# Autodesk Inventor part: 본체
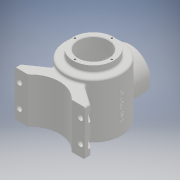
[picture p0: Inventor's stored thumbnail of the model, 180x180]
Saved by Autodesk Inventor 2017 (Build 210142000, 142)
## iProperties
Part Number: 본체
Material: 일반
Document SubType Name: Modeling
Designer: MRC
Density: 1 g/cm^3
Appearance: 기본값
Author: MRC
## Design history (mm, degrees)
sketch "스케치1"
  geometry: L1 (0, 50)-(0, -58); L2 (50, 50)-(50, -46.336); L3 (50, 50)-(0, 50); A1 r 113 centre (0, 55) between (0, -58) and (50, -46.336); 1 further point
  constraints: 6 end point, 2 point on circle, 2 point on line, 2 vertical, 1 centre point, 1 horizontal
  dimensions: "d0" = 108 distance of L1.start L1.end; "d1" = 50 distance of L1.start point (0, 0); "d3" = 100 diameter of L2 L1; "d4" = 113 radius of A1
revolve "회전1" sketch "스케치1" stored, may be unused: angle "d5" = 90 deg
feature "쉘1" dims "d6" = 7
sketch "스케치2"
  geometry: C1 r 36 at (0, 0); 1 further point
  constraints: 1 centre point, 1 coincident
  dimensions: "d7" = 72 diameter of C1
extrude "돌출1" join sketch "스케치2" distance "d8" = 12; taper "d9" = 0 deg
sketch "스케치3"
  geometry: C1 r 27 at (0, 0); 1 further point
  constraints: 1 centre point, 1 coincident
  dimensions: "d10" = 54 diameter of C1
extrude "돌출2" cut sketch "스케치3" distance "d11" = 19; taper "d12" = 0 deg
sketch "스케치4"
  geometry: L1 (-26.694, -42.278)-(-62, -67); L2 (-62, -67)-(-62, -77); L3 (-62, -77)-(-38.5, -77); L4 (38.5, -77)-(62, -77); L5 (62, -77)-(62, -67); L6 (62, -67)-(26.694, -42.278); A1 r 52.096 centre (0, -112.096) between (38.5, -77) and (-38.5, -77); A2 r 50 centre (0, 0) between (26.694, -42.278) and (-26.694, -42.278) reference; 1 further point
  constraints: 12 end point, 4 point on circle, 2 perpendicular, 1 centre point, 1 collinear, 1 horizontal, 1 vertical, 1 vertical alignment
  dimensions: "d13" = 10 distance of L4.end L5.end; "d14" = 77 distance of L4.start L3.end; "d15" = 55 deg angle of L5 L6; "d16" = 10 distance of L1.end L2.end; "d17" = 77 distance from line of L4 point (0, 0); "d18" = 77 distance from line of point (0, 0) L3; "d19" = 124 distance between parallel lines of L5 L2; "d20" = 17 distance edge to line of A1 L4; "d26" = 55 deg angle of L2 L1
extrude "돌출3" join sketch "스케치4" distance "d23" = 42; taper "d24" = 0 deg; dims "d88" = 38, "d89" = 0
node "작업 평면1"
sketch "스케치5"
  geometry: C1 r 36 at (-38.5, -42); 1 further point
  constraints: 1 centre point, 1 coincident
  dimensions: "d28" = 72 diameter of C1
extrude "돌출4" join sketch "스케치5" stored distance "d29" = 10; taper "d30" = 0 deg
sketch "스케치6"
  geometry: C1 r 27 at (0, 0); 1 further point
  constraints: 1 centre point, 1 coincident
  dimensions: "d31" = 54 diameter of C1
extrude "돌출5" cut sketch "스케치6" distance "d32" = 41.5; taper "d33" = 0 deg
sketch "스케치7" dims "d34" = 65
  geometry: 3 further points
  constraints: 2 horizontal alignment, 1 coincident, 2 other
hole "구멍1" sketch "스케치7" at (-32.5, 0) diameter "d35" = 3.242; stored, may be unused: countersink angle "d39" = 90 deg, drill point angle "d41" = 118 deg; dims "d36" = 8, "d37" = 4, "d38" = 2, "d40" = 10
sketch "스케치12" dims "d58" = 65
  geometry: 3 further points
  constraints: 2 vertical alignment, 1 coincident, 2 other
hole "구멍2" sketch "스케치12" at (0, 32.5) diameter "d59" = 3.242; stored, may be unused: countersink angle "d63" = 90 deg, drill point angle "d65" = 118 deg; dims "d60" = 8, "d61" = 4, "d62" = 2, "d64" = 10
sketch "스케치9"
  geometry: L1 (23.5, -80)-(23.5, 0) reference; L2 (23.5, -80)-(0, -80) reference; C1 r 4.5 at (15.5, -60); 1 further point
  constraints: 1 centre point
  dimensions: "d49" = 9 diameter of C1; "d50" = 8 distance from line of L1 C1.centre; "d51" = 20 distance from line of L2 C1.centre
extrude "돌출6" cut sketch "스케치9" distance "d52" = 6; taper "d53" = 0 deg
sketch "스케치13"
  geometry: L1 (0, 0)-(24.644, 0); L2 (0, -7)-(24.644, -7); L3 (24.644, 7)-(0, 7); L4 (8, -20)-(8, 60) reference; L5 (-27.306, -20)-(8, -20) reference; A1 r 7 centre (0, 0) between (0, 7) and (0, -7); A2 r 7 centre (24.644, 0) between (24.644, -7) and (24.644, 7); 2 further points
  constraints: 8 end point, 4 point on circle, 4 tangent, 2 centre point, 1 horizontal, 1 midpoint, 1 parallel
  dimensions: "d69" = 14 diameter of A2; "d70" = 8 distance from line of L4 L1.start; "d71" = 20 distance from line of L5 L1.start; "d72" = 24.64379 distance of L3.start L3.end
extrude "돌출8" cut sketch "스케치13" distance "d73" = 20; taper "d74" = 0 deg
fillet "모깎기1" dims "d78" = 3
fillet "모깎기2" dims "d79" = 3
fillet "모깎기3" dims "d80" = 3
fillet "모깎기4" dims "d81" = 3
fillet "모깎기5" dims "d82" = 3
chamfer "모따기1" distance "d83" = 1; stored, may be unused: second distance "d84" = 2, angle "d85" = 45 deg
fillet "모깎기6" dims "d86" = 3
node "작업 평면3"
sketch "스케치14"
  geometry: L1 (36, 62)-(-36, 62) reference; 2 further points
  constraints: 2 coincident, 1 other
  dimensions: "d90" = 62 distance from line of point (0, 0) L1 (derived)
feature "엠보싱1" sketch "스케치14" dims "d91" = 0.5, "d92" = 0
node "솔리드1"
pattern_circular "원형 패턴1" dims angle "d43" = 360 deg
pattern_circular "원형 패턴2" dims angle "d67" = 360 deg
pattern_linear "직사각형 패턴1" dims "d77" = 40
mirror "미러1"
other parameters: "d27" = -142, "d87" = 82.25
